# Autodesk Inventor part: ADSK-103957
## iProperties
Shininess: 0.0
Created: 2000-09
Part Number: ADSK-103957
Document SubType Name: Modeling
Stock Number: ADSK-103957
Density: 1 g/cm^3
Density: 0.0
Volumn: 0.0
Area: 0.0
PropertySet Name: Model Information
Control State: 0
Master: False
Checked Out: False
Author: gao
